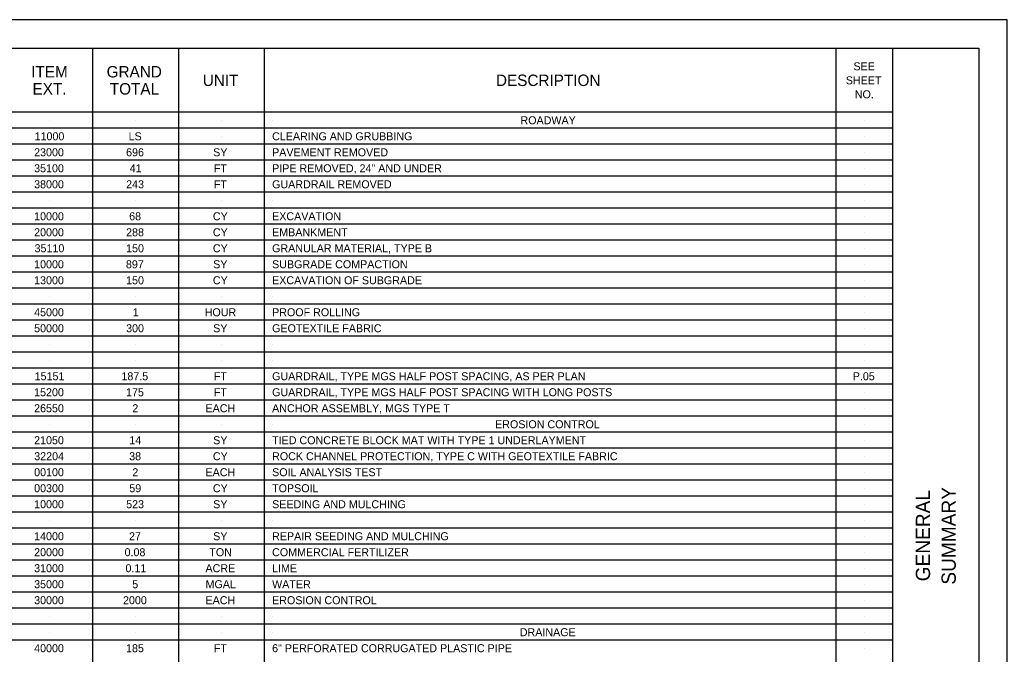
# Model space of a CAD drawing. Extents: x 0 to 34, y 0 to 22.
# Drawn here: x 16.73 to 34, y 10.89 to 22 of the extents above; entities that cross this region are included whole.
import ezdxf

# ---------------------------------------------------------------- set-up
doc = ezdxf.new("R2010")
doc.units = 0
for name, color, linetype in [('RD_P_Text', 7, 'Continuous'), ('SC_Scratch1', 7, 'Continuous'), ('SH_Border', 7, 'Continuous'), ('SH_Cut_Line', 7, 'Continuous'), ('SH_Data', 7, 'Continuous')]:
    doc.layers.add(name, color=color, linetype=linetype)

msp = doc.modelspace()

# ---------------------------------------------------------------- linework, layer by layer
at = {"layer": 'SC_Scratch1'}
for p, q in [((17.25, 20.24), (17.25, 20.24)), ((18.75, 20.24), (18.75, 20.24)), ((20.25, 20.24), (20.25, 20.24)), ((21.14, 20.24), (21.14, 20.24)), ((31.5, 20.24), (31.5, 20.24)), ((17.25, 19.96), (17.25, 19.96)), ((18.75, 19.96), (18.75, 19.96)), ((20.25, 19.96), (20.25, 19.96)), ((21.14, 19.96), (21.14, 19.96)), ((31.5, 19.96), (31.5, 19.96)), ((17.25, 19.68), (17.25, 19.68)), ((18.75, 19.68), (18.75, 19.68)), ((20.25, 19.68), (20.25, 19.68)), ((21.14, 19.68), (21.14, 19.68)), ((31.5, 19.68), (31.5, 19.68)), ((17.25, 19.4), (17.25, 19.4)), ((18.75, 19.4), (18.75, 19.4)), ((20.25, 19.4), (20.25, 19.4)), ((21.14, 19.4), (21.14, 19.4)), ((31.5, 19.4), (31.5, 19.4)), ((17.25, 19.12), (17.25, 19.12)), ((18.75, 19.12), (18.75, 19.12)), ((20.25, 19.12), (20.25, 19.12)), ((21.14, 19.12), (21.14, 19.12)), ((31.5, 19.12), (31.5, 19.12)), ((17.25, 18.84), (17.25, 18.84)), ((18.75, 18.84), (18.75, 18.84)), ((20.25, 18.84), (20.25, 18.84)), ((21.14, 18.84), (21.14, 18.84)), ((31.5, 18.84), (31.5, 18.84)), ((17.25, 18.56), (17.25, 18.56)), ((18.75, 18.56), (18.75, 18.56)), ((20.25, 18.56), (20.25, 18.56)), ((21.14, 18.56), (21.14, 18.56)), ((31.5, 18.56), (31.5, 18.56)), ((17.25, 18.28), (17.25, 18.28)), ((18.75, 18.28), (18.75, 18.28)), ((20.25, 18.28), (20.25, 18.28)), ((21.14, 18.28), (21.14, 18.28)), ((31.5, 18.28), (31.5, 18.28)), ((17.25, 18), (17.25, 18)), ((18.75, 18), (18.75, 18)), ((20.25, 18), (20.25, 18)), ((21.14, 18), (21.14, 18)), ((31.5, 18), (31.5, 18)), ((17.25, 17.72), (17.25, 17.72)), ((18.75, 17.72), (18.75, 17.72)), ((20.25, 17.72), (20.25, 17.72)), ((21.14, 17.72), (21.14, 17.72)), ((31.5, 17.72), (31.5, 17.72)), ((17.25, 17.44), (17.25, 17.44)), ((18.75, 17.44), (18.75, 17.44)), ((20.25, 17.44), (20.25, 17.44)), ((21.14, 17.44), (21.14, 17.44)), ((31.5, 17.44), (31.5, 17.44)), ((17.25, 17.16), (17.25, 17.16)), ((18.75, 17.16), (18.75, 17.16)), ((20.25, 17.16), (20.25, 17.16)), ((21.14, 17.16), (21.14, 17.16)), ((31.5, 17.16), (31.5, 17.16)), ((17.25, 16.88), (17.25, 16.88)), ((18.75, 16.88), (18.75, 16.88)), ((20.25, 16.88), (20.25, 16.88)), ((21.14, 16.88), (21.14, 16.88)), ((31.5, 16.88), (31.5, 16.88)), ((17.25, 16.6), (17.25, 16.6)), ((18.75, 16.6), (18.75, 16.6)), ((20.25, 16.6), (20.25, 16.6)), ((21.14, 16.6), (21.14, 16.6)), ((31.5, 16.6), (31.5, 16.6)), ((17.25, 16.32), (17.25, 16.32)), ((18.75, 16.32), (18.75, 16.32)), ((20.25, 16.32), (20.25, 16.32)), ((21.14, 16.32), (21.14, 16.32)), ((31.5, 16.32), (31.5, 16.32)), ((17.25, 16.04), (17.25, 16.04)), ((18.75, 16.04), (18.75, 16.04)), ((20.25, 16.04), (20.25, 16.04)), ((21.14, 16.04), (21.14, 16.04)), ((31.5, 16.04), (31.5, 16.04)), ((17.25, 15.76), (17.25, 15.76)), ((18.75, 15.76), (18.75, 15.76)), ((20.25, 15.76), (20.25, 15.76)), ((21.14, 15.76), (21.14, 15.76)), ((31.5, 15.76), (31.5, 15.76)), ((17.25, 15.48), (17.25, 15.48)), ((18.75, 15.48), (18.75, 15.48)), ((20.25, 15.48), (20.25, 15.48)), ((21.14, 15.48), (21.14, 15.48)), ((31.5, 15.48), (31.5, 15.48)), ((17.25, 15.2), (17.25, 15.2)), ((18.75, 15.2), (18.75, 15.2)), ((20.25, 15.2), (20.25, 15.2)), ((21.14, 15.2), (21.14, 15.2)), ((31.5, 15.2), (31.5, 15.2)), ((17.25, 14.92), (17.25, 14.92)), ((18.75, 14.92), (18.75, 14.92)), ((20.25, 14.92), (20.25, 14.92)), ((21.14, 14.92), (21.14, 14.92)), ((31.5, 14.92), (31.5, 14.92)), ((17.25, 14.64), (17.25, 14.64)), ((18.75, 14.64), (18.75, 14.64)), ((20.25, 14.64), (20.25, 14.64)), ((21.14, 14.64), (21.14, 14.64)), ((31.5, 14.64), (31.5, 14.64)), ((17.25, 14.36), (17.25, 14.36)), ((18.75, 14.36), (18.75, 14.36)), ((20.25, 14.36), (20.25, 14.36)), ((21.14, 14.36), (21.14, 14.36)), ((31.5, 14.36), (31.5, 14.36)), ((17.25, 14.08), (17.25, 14.08)), ((18.75, 14.08), (18.75, 14.08)), ((20.25, 14.08), (20.25, 14.08)), ((21.14, 14.08), (21.14, 14.08)), ((31.5, 14.08), (31.5, 14.08)), ((17.25, 13.8), (17.25, 13.8)), ((18.75, 13.8), (18.75, 13.8)), ((20.25, 13.8), (20.25, 13.8)), ((21.14, 13.8), (21.14, 13.8)), ((31.5, 13.8), (31.5, 13.8)), ((17.25, 13.52), (17.25, 13.52)), ((18.75, 13.52), (18.75, 13.52)), ((20.25, 13.52), (20.25, 13.52)), ((21.14, 13.52), (21.14, 13.52)), ((31.5, 13.52), (31.5, 13.52)), ((17.25, 13.24), (17.25, 13.24)), ((18.75, 13.24), (18.75, 13.24)), ((20.25, 13.24), (20.25, 13.24)), ((21.14, 13.24), (21.14, 13.24)), ((31.5, 13.24), (31.5, 13.24)), ((17.25, 12.96), (17.25, 12.96)), ((18.75, 12.96), (18.75, 12.96)), ((20.25, 12.96), (20.25, 12.96)), ((21.14, 12.96), (21.14, 12.96)), ((31.5, 12.96), (31.5, 12.96)), ((17.25, 12.68), (17.25, 12.68)), ((18.75, 12.68), (18.75, 12.68)), ((20.25, 12.68), (20.25, 12.68)), ((21.14, 12.68), (21.14, 12.68)), ((31.5, 12.68), (31.5, 12.68)), ((17.25, 12.4), (17.25, 12.4)), ((18.75, 12.4), (18.75, 12.4)), ((20.25, 12.4), (20.25, 12.4)), ((21.14, 12.4), (21.14, 12.4)), ((31.5, 12.4), (31.5, 12.4)), ((17.25, 12.12), (17.25, 12.12)), ((18.75, 12.12), (18.75, 12.12)), ((20.25, 12.12), (20.25, 12.12)), ((21.14, 12.12), (21.14, 12.12)), ((31.5, 12.12), (31.5, 12.12)), ((17.25, 11.84), (17.25, 11.84)), ((18.75, 11.84), (18.75, 11.84)), ((20.25, 11.84), (20.25, 11.84)), ((21.14, 11.84), (21.14, 11.84)), ((31.5, 11.84), (31.5, 11.84)), ((17.25, 11.56), (17.25, 11.56)), ((18.75, 11.56), (18.75, 11.56)), ((20.25, 11.56), (20.25, 11.56)), ((21.14, 11.56), (21.14, 11.56)), ((31.5, 11.56), (31.5, 11.56)), ((17.25, 11.28), (17.25, 11.28)), ((18.75, 11.28), (18.75, 11.28)), ((20.25, 11.28), (20.25, 11.28)), ((21.14, 11.28), (21.14, 11.28)), ((31.5, 11.28), (31.5, 11.28)), ((17.25, 11), (17.25, 11)), ((18.75, 11), (18.75, 11)), ((20.25, 11), (20.25, 11)), ((21.14, 11), (21.14, 11)), ((31.5, 11), (31.5, 11))]:
    msp.add_line(p, q, dxfattribs=at)
at = {"layer": 'SH_Border'}
msp.add_line((32, 0.5), (32, 21.5), dxfattribs=at)
msp.add_lwpolyline([(1.5, 21.5), (33.5, 21.5), (33.5, 0.5), (1.5, 0.5)], close=True, dxfattribs=at)
at = {"layer": 'SH_Cut_Line'}
msp.add_lwpolyline([(0, 0), (34, 0), (34, 22), (0, 22)], close=True, dxfattribs=at)
at = {"layer": 'SH_Data'}
for p, q in [((18, 21.5), (18, 0.5)), ((19.5, 21.5), (19.5, 0.5)), ((21, 21.5), (21, 0.5)), ((31, 21.5), (31, 0.5)), ((32, 20.38), (1.5, 20.38)), ((32, 20.1), (1.5, 20.1)), ((32, 19.82), (1.5, 19.82)), ((32, 19.54), (1.5, 19.54)), ((32, 19.26), (1.5, 19.26)), ((32, 18.98), (1.5, 18.98)), ((32, 18.7), (1.5, 18.7)), ((32, 18.42), (1.5, 18.42)), ((32, 18.14), (1.5, 18.14)), ((32, 17.86), (1.5, 17.86)), ((32, 17.58), (1.5, 17.58)), ((32, 17.3), (1.5, 17.3)), ((32, 17.02), (1.5, 17.02)), ((32, 16.74), (1.5, 16.74)), ((32, 16.46), (1.5, 16.46)), ((32, 16.18), (1.5, 16.18)), ((32, 15.9), (1.5, 15.9)), ((32, 15.62), (1.5, 15.62)), ((32, 15.34), (1.5, 15.34)), ((32, 15.06), (1.5, 15.06)), ((32, 14.78), (1.5, 14.78)), ((32, 14.5), (1.5, 14.5)), ((32, 14.22), (1.5, 14.22)), ((32, 13.94), (1.5, 13.94)), ((32, 13.66), (1.5, 13.66)), ((32, 13.38), (1.5, 13.38)), ((32, 13.1), (1.5, 13.1)), ((32, 12.82), (1.5, 12.82)), ((32, 12.54), (1.5, 12.54)), ((32, 12.26), (1.5, 12.26)), ((32, 11.98), (1.5, 11.98)), ((32, 11.7), (1.5, 11.7)), ((32, 11.42), (1.5, 11.42)), ((32, 11.14), (1.5, 11.14))]:
    msp.add_line(p, q, dxfattribs=at)

# ---------------------------------------------------------------- texts
at = {"layer": 'RD_P_Text'}
for s, p in [('ROADWAY', (25.485, 20.17)), ('11000', (16.985, 19.89)), ('LS', (18.63, 19.89)), ('CLEARING AND GRUBBING', (21.14, 19.89)), ('23000', (16.977, 19.61)), ('696', (18.586, 19.61)), ('SY', (20.109, 19.61)), ('PAVEMENT REMOVED', (21.14, 19.61)), ('35100', (16.977, 19.33)), ('41', (18.649, 19.33)), ('FT', (20.121, 19.33)), ('PIPE REMOVED, 24" AND UNDER', (21.14, 19.33)), ('38000', (16.977, 19.05)), ('243', (18.587, 19.05)), ('FT', (20.121, 19.05)), ('GUARDRAIL REMOVED', (21.14, 19.05)), ('10000', (16.977, 18.49)), ('68', (18.64, 18.49)), ('CY', (20.104, 18.49)), ('EXCAVATION', (21.14, 18.49)), ('20000', (16.977, 18.21)), ('288', (18.586, 18.21)), ('CY', (20.104, 18.21)), ('EMBANKMENT', (21.14, 18.21)), ('35110', (16.985, 17.93)), ('150', (18.586, 17.93)), ('CY', (20.104, 17.93)), ('GRANULAR MATERIAL, TYPE B', (21.14, 17.93)), ('10000', (16.977, 17.65)), ('897', (18.583, 17.65)), ('SY', (20.109, 17.65)), ('SUBGRADE COMPACTION', (21.14, 17.65)), ('13000', (16.977, 17.37)), ('150', (18.586, 17.37)), ('CY', (20.104, 17.37)), ('EXCAVATION OF SUBGRADE', (21.14, 17.37)), ('45000', (16.977, 16.81)), ('1', (18.703, 16.81)), ('HOUR', (19.961, 16.81)), ('PROOF ROLLING', (21.14, 16.81)), ('50000', (16.977, 16.53)), ('300', (18.586, 16.53)), ('SY', (20.109, 16.53)), ('GEOTEXTILE FABRIC', (21.14, 16.53)), ('15151', (16.986, 15.69)), ('187.5', (18.504, 15.69)), ('FT', (20.121, 15.69)), ('GUARDRAIL, TYPE MGS HALF POST SPACING, AS PER PLAN', (21.14, 15.69)), ('P.05', (31.297, 15.69)), ('15200', (16.977, 15.41)), ('175', (18.585, 15.41)), ('FT', (20.121, 15.41)), ('GUARDRAIL, TYPE MGS HALF POST SPACING WITH LONG POSTS', (21.14, 15.41)), ('26550', (16.977, 15.13)), ('2', (18.695, 15.13)), ('EACH', (19.975, 15.13)), ('ANCHOR ASSEMBLY, MGS TYPE T', (21.14, 15.13)), ('EROSION CONTROL', (25.041, 14.85)), ('21050', (16.977, 14.57)), ('14', (18.642, 14.57)), ('SY', (20.109, 14.57)), ('TIED CONCRETE BLOCK MAT WITH TYPE 1 UNDERLAYMENT', (21.14, 14.57)), ('32204', (16.979, 14.29)), ('38', (18.64, 14.29)), ('CY', (20.104, 14.29)), ('ROCK CHANNEL PROTECTION, TYPE C WITH GEOTEXTILE FABRIC', (21.14, 14.29)), ('00100', (16.977, 14.01)), ('2', (18.695, 14.01)), ('EACH', (19.975, 14.01)), ('SOIL ANALYSIS TEST', (21.14, 14.01)), ('00300', (16.977, 13.73)), ('59', (18.642, 13.73)), ('CY', (20.104, 13.73)), ('TOPSOIL', (21.14, 13.73)), ('10000', (16.977, 13.45)), ('523', (18.587, 13.45)), ('SY', (20.109, 13.45)), ('SEEDING AND MULCHING', (21.14, 13.45)), ('14000', (16.977, 12.89)), ('27', (18.637, 12.89)), ('SY', (20.109, 12.89)), ('REPAIR SEEDING AND MULCHING', (21.14, 12.89)), ('20000', (16.977, 12.61)), ('0.08', (18.559, 12.61)), ('TON', (20.042, 12.61)), ('COMMERCIAL FERTILIZER', (21.14, 12.61)), ('31000', (16.977, 12.33)), ('0.11', (18.575, 12.33)), ('ACRE', (19.974, 12.33)), ('LIME', (21.14, 12.33)), ('35000', (16.977, 12.05)), ('5', (18.694, 12.05)), ('MGAL', (19.976, 12.05)), ('WATER', (21.14, 12.05)), ('30000', (16.977, 11.77)), ('2000', (18.532, 11.77)), ('EACH', (19.975, 11.77)), ('EROSION CONTROL', (21.14, 11.77)), ('DRAINAGE', (25.473, 11.21)), ('40000', (16.977, 10.93)), ('185', (18.585, 10.93)), ('FT', (20.121, 10.93)), ('6" PERFORATED CORRUGATED PLASTIC PIPE', (21.14, 10.93))]:
    msp.add_text(s, height=0.14, dxfattribs=at).set_placement(p)
at = {"layer": 'SH_Data'}
for s, height, p in [('SEE', 0.14, (31.309, 21.115)), ('ITEM', 0.2, (16.926, 20.99)), ('GRAND', 0.2, (18.245, 20.99)), ('UNIT', 0.2, (19.927, 20.84)), ('DESCRIPTION', 0.2, (25.056, 20.84)), ('SHEET', 0.14, (31.176, 20.87)), ('EXT.', 0.2, (16.949, 20.69)), ('TOTAL', 0.2, (18.301, 20.69)), ('NO.', 0.14, (31.333, 20.625))]:
    msp.add_text(s, height=height, dxfattribs=at).set_placement(p)
for s, p in [('GENERAL', (32.65, 12.171)), ('SUMMARY', (33.1, 12.112))]:
    msp.add_text(s, height=0.25, rotation=90, dxfattribs=at).set_placement(p)

doc.saveas('drawing.dxf')
